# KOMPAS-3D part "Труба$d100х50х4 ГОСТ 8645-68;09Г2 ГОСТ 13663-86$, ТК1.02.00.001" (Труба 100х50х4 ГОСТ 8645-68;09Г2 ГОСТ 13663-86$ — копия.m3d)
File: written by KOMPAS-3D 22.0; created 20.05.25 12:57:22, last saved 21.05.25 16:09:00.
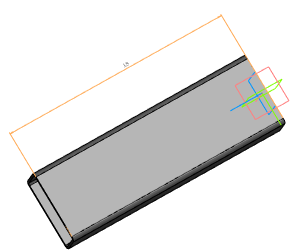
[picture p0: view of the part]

Document properties: Автор: TC; Полное имя файла: D:\Рабочая папка\АРХИВ\612\05\Задание №6 - Тележка для крыши\3Д\Рама направляющих\Труба 100х50х4 ГОСТ 8645-68;09Г2 ГОСТ 13663-86$ — копия.m3d

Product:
- Part/product: Труба$d100х50х4 ГОСТ 8645-68;09Г2 ГОСТ 13663-86$  | designation ТК1.02.00.001
    Материал: Труба$d80х40х7 ГОСТ 8645-68;09Г2 ГОСТ 13663-86$ (density 7850 kg/m3)
    Масса: 2.076019
    Раздел спецификации: Детали
    Форматы листов документа: б/ч
    Примечание: m=2.07 кг / L=315 мм

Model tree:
1. Эскиз:1
2. Элемент выдавливания:1
     Толщина стенки 2 = 3; Расстояние 1 = 315
3. Скругление:1  (with: Элемент выдавливания:1)
     Радиус = 3
4. Скругление:2  (with: Элемент выдавливания:1)
     Радиус = 6
5. Эскиз:2  (with: Элемент выдавливания:1)
6. Элемент выдавливания:2
     Расстояние 2 = 10
7. Линейный размер:1  (with: Элемент выдавливания:1, Скругление:2)  (labels: Труба$d80х40х7 ГОСТ 8645-68;09Г2 ГОСТ 13663-86$; BOSimple***SortamentEx:4194d098-baf7-48ce-a229-ad4525d580d6)
     Значение = 315

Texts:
  ТК1.02.00.001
